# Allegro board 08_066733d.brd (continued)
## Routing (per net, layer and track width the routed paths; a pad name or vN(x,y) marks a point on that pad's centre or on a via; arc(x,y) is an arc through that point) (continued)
DMC0_DQ10: length 33.4
  TOP w0.203: U1.B12 v1(34.62,60.54) ; U8.C8 v1(29.02,79.14)
  BOTTOM w0.14: v1(34.62,60.54) 35.02,60.14 37.02,60.14 37.42,60.54 37.42,62.54 37.22,62.74 35.22,62.74 34.82,63.14 34.82,63.43 34.82,63.43 34.82,64.25 34.82,64.25 34.82,64.43 34.82,64.43 34.82,64.74 34.02,65.54 32.82,65.54 32.42,65.94 32.42,68.34 31.82,68.94 31.82,69.94 32.62,70.74 32.62,76.34 31.82,77.14 31.82,80.54 31.42,80.94 29.82,80.94 29.42,80.54 29.42,79.54 v1(29.02,79.14)
DMC0_DQ11: length 33.4
  TOP w0.203: U1.B10 v1(33.02,60.54) ; v1(28.22,73.54) 28.59,73.91 28.59,73.91 U8.C2
  BOTTOM w0.14: v1(28.22,73.54) 27.82,73.14 27.82,68.34 28.22,67.94 29.21,67.94 29.34,67.81 29.34,66.17 29.21,66.04 28.96,66.04 28.83,66.17 28.83,67.18 28.7,67.31 26.67,67.31 26.54,67.18 26.54,66.93 26.67,66.8 28.32,66.8 28.45,66.67 28.45,66.55 28.32,66.42 27.69,66.42 27.56,66.29 27.56,66.1 27.69,65.98 28.32,65.98 28.45,65.85 28.45,65.09 28.32,64.96 27.69,64.96 27.56,64.83 27.56,64.64 27.69,64.52 28.32,64.52 28.45,64.39 28.45,64.2 28.32,64.07 27.69,64.07 27.56,63.94 27.56,63.75 27.69,63.63 28.83,63.63 28.96,63.75 28.96,64.9 29.08,65.02 29.34,65.02 29.46,64.9 29.46,63.75 29.59,63.63 32.26,63.63 32.51,63.37 32.51,62.61 33.02,62.1 v1(33.02,60.54)
DMC0_DQ12: length 33.5
  TOP w0.203: v1(31.42,59.74) U1.C9 ; v1(26.62,78.34) 26.99,77.97 U8.A7
  BOTTOM w0.14: v1(31.42,59.74) 30.42,59.74 30.02,60.14 25.36,60.14 24.22,61.28 24.22,79.96 24.4,80.14 24.64,80.14 24.76,80.01 24.76,79.12 24.89,78.99 25.15,78.99 25.27,79.12 25.27,80.01 25.4,80.14 25.91,80.14 26.22,79.83 26.22,78.74 v1(26.62,78.34)
DMC0_DQ13: length 33.5
  TOP w0.203: U8.A2 27.05,73.97 v1(27.42,74.34) ; U1.A12 v1(33.82,61.34)
  BOTTOM w0.14: v1(33.82,61.34) 34.8,61.34 35.1,61.34 35.23,61.47 35.23,61.81 35.1,61.94 34.22,61.94 33.82,62.34 33.82,64.13 33.44,64.52 31.62,64.52 31.11,65.02 31.11,68.56 31.02,68.65 31.02,70.14 30.62,70.54 28.82,70.54 28.62,70.74 28.62,70.94 28.82,71.14 30.82,71.14 31.22,70.74 31.42,70.74 31.82,71.14 31.82,71.54 31.62,71.74 30.82,71.74 30.62,71.94 30.62,72.14 31.02,72.54 31.02,75.54 30.82,75.74 30.82,76.74 30.62,76.94 30.42,76.94 30.22,76.74 30.22,74.94 30.02,74.74 27.82,74.74 v1(27.42,74.34)
DMC0_DQ14: length 33.5
  TOP w0.203: v1(31.42,58.94) U1.D8 ; v1(27.42,79.14) 27.79,78.77 U8.B8
  BOTTOM w0.14: v1(27.42,79.14) 27.02,79.54 27.02,80.34 26.82,80.54 24.22,80.54 23.82,80.14 23.82,61.12 25.6,59.34 31.02,59.34 v1(31.42,58.94)
DMC0_DQ15: length 33.5
  TOP w0.203: v1(26.62,74.34) 26.99,74.71 26.99,74.71 U8.A3 ; v1(32.22,60.54) U1.B9
  BOTTOM w0.14: v1(26.62,74.34) 26.39,74.52 26.36,74.55 26.15,74.55 26.02,74.42 26.02,73.99 26.22,73.79 26.77,73.79 26.97,73.59 26.97,73.48 26.77,73.28 26.22,73.28 26.02,73.08 26.02,72.14 26.22,71.94 27.02,71.94 27.22,71.74 27.22,71.54 27.02,71.34 26.22,71.34 26.02,71.14 26.02,70.94 26.22,70.74 27.02,70.74 27.22,70.54 27.22,70.34 27.02,70.14 26.22,70.14 26.02,69.94 26.02,69.74 26.22,69.54 27.02,69.54 27.22,69.34 27.22,69.14 27.02,68.94 26.22,68.94 26.02,68.74 26.02,68.54 26.22,68.34 27.02,68.34 27.22,68.14 27.22,67.94 27.02,67.74 26.22,67.74 26.02,67.54 26.02,66.8 27.18,65.64 27.18,63.25 27.69,62.74 31.82,62.74 32.62,61.94 32.62,61.14 32.42,60.94 31.02,60.94 30.82,60.74 30.82,60.34 31.02,60.14 U1.B9 v1(32.22,60.54)
DMC0_LDM: length 33.4
  TOP w0.203: U8.E7 v1(29.82,78.34) ; v1(30.62,57.34) U1.E8
  L4_SIG w0.127: v1(30.62,57.34) 30.22,57.74 26.22,57.74 25.29,58.67 23.88,58.67 23.49,59.05 23.49,76.33 25.11,77.94 29.42,77.94 v1(29.82,78.34)
DMC0_LDQS: length 33.3
  TOP w0.203: v1(30.62,75.14) 30.99,74.77 U8.F3 ; U1.A6 v1(29.02,61.34)
  L4_SIG w0.076: v1(30.62,75.14) 30.72,74.94 30.7,74.83 30.35,74.49 30.35,73.47 29.72,72.83 29.72,72.14 29.97,71.88 29.97,71.63 29.59,71.25 29.59,70.74 29.97,70.36 29.97,67.18 29.84,67.06 26.92,67.06 26.67,66.8 26.67,66.29 26.92,66.04 29.84,66.04 29.97,65.91 29.97,65.28 29.84,65.15 26.92,65.15 26.67,64.9 26.67,64.45 26.92,64.2 30.1,64.2 30.23,64.07 30.23,63.88 30.1,63.76 27.43,63.76 27.18,63.5 27.18,62.75 27.43,62.5 29.21,62.5 29.46,62.24 29.46,61.86 v1(29.02,61.34)
DMC0_LDQS*: length 33.3
  TOP w0.203: U8.G3 31.79,74.77 v1(31.42,75.14) ; U1.A7 v1(29.82,61.34)
  L4_SIG w0.076: v1(29.82,61.34) 29.72,61.73 29.72,62.37 29.34,62.75 27.56,62.75 27.43,62.88 27.43,63.39 27.54,63.5 30.21,63.5 30.48,63.78 30.48,64.18 30.2,64.45 27.05,64.45 26.92,64.58 26.92,64.77 27.05,64.9 29.97,64.9 30.23,65.15 30.23,66.04 29.97,66.29 27.05,66.29 26.92,66.42 26.92,66.67 27.05,66.8 29.97,66.8 30.23,67.06 30.23,70.48 29.84,70.87 29.84,71.12 30.23,71.5 30.23,72.01 29.97,72.26 29.97,72.71 30.61,73.34 30.61,74.33 v1(31.42,75.14)
DMC0_ODT: length 41.2
  TOP w0.203: U8.K1 v1(33.82,72.74) ; v1(38.62,59.74) U1.B18
  L8_SIG w0.127: v1(33.82,72.74) 33.82,72.14 33.42,71.74 31.02,71.74 30.82,71.54 30.82,71.34 31.02,71.14 32.02,71.14 32.22,70.94 32.22,70.74 32.02,70.54 30.82,70.54 30.62,70.34 30.62,70.14 30.82,69.94 31.62,69.94 31.82,69.74 31.82,69.14 31.62,68.94 30.82,68.94 30.62,68.74 30.62,68.54 30.82,68.34 31.82,68.34 32.02,68.14 32.02,67.94 31.82,67.74 30.82,67.74 30.62,67.54 30.62,66.42 31.11,65.93 31.11,62.38 31.82,61.67 31.82,58.74 32.02,58.54 37.22,58.54 37.42,58.74 37.42,59.14 37.62,59.34 38.22,59.34 v1(38.62,59.74)
  BOTTOM w0.14: RN6.2 33.57,69.44 33.42,69.59 33.42,69.94 33.62,70.14 33.82,70.14 34.02,69.94 34.42,69.94 34.62,70.14 34.62,70.34 34.42,70.54 33.62,70.54 33.42,70.74 33.42,70.94 33.62,71.14 33.82,71.14 34.02,70.94 34.42,70.94 34.62,71.14 34.62,71.34 34.42,71.54 33.82,71.54 33.42,71.94 33.42,72.34 v1(33.82,72.74)
DMC0_RAS*: length 41.2
  TOP w0.203: v1(37.82,58.14) U1.D16 ; v1(33.02,74.34) 33.39,74.71 33.39,74.71 U8.J3
  L8_SIG w0.127: v1(37.82,58.14) 37.42,57.74 35.22,57.74 34.82,57.34 34.42,57.34 34.02,57.74 32.02,57.74 31.62,57.34 31.22,57.34 31.02,57.54 31.02,61.74 30.22,62.54 30.22,71.94 30.42,72.14 32.82,72.14 33.02,72.34 33.02,72.94 32.82,73.14 30.82,73.14 30.62,73.34 30.62,73.74 30.82,73.94 32.62,73.94 v1(33.02,74.34)
  BOTTOM w0.14: v1(33.02,74.34) 33.02,75.34 33.22,75.54 33.42,75.54 33.62,75.34 33.62,74.94 U8.J3 33.42,73.34 33.02,72.94 33.02,68.84 RN6.1
DMC0_RESET*: length 29.5
  TOP w0.14: U8.T2 39.6,73.35 39.6,72.32 39.22,71.94 R8.2
  TOP w0.203: v1(33.02,58.14) U1.D10 ; U8.T2 v1(38.62,73.54)
  L5_SIG w0.127: v1(33.02,58.14) 33.42,58.54 33.42,62.1 34.04,62.72 34.04,67.06 38.22,71.24 38.22,73.14 v1(38.62,73.54)
  BOTTOM w0.14: RN2.1 42.22,72.85 42.22,72.64 42.46,72.4 42.48,72.36 42.48,72.34 42.48,72.33 42.48,71.9 42.42,71.84 42.42,71.74 42.02,71.34 39.42,71.34 39.02,71.74 39.02,73.14 v1(38.62,73.54)
DMC0_RZQ: length 11.1
  TOP w0.203: v1(37.82,60.54) U1.B16
  BOTTOM w0.14: R1.1 42.82,54.94 42.29,55.47 42.29,59.47 41.62,60.14 38.22,60.14 v1(37.82,60.54)
DMC0_UDM: length 33.5
  TOP w0.203: U1.D12 v1(33.82,58.94) ; v1(29.02,75.14) 29.39,74.77 U8.D3
  BOTTOM w0.14: v1(29.02,75.14) 29.82,75.94 29.82,77.64 30.22,78.04 30.22,79.34 30.42,79.54 30.82,79.54 31.02,79.34 31.02,77.14 31.82,76.34 31.82,72.34 32.22,71.94 32.22,70.94 31.42,70.14 31.42,68.74 31.62,68.54 31.62,65.91 31.5,65.79 31.5,65.28 31.75,65.02 33.91,65.02 34.42,64.52 34.42,62.84 34.92,62.34 35.94,62.34 36.07,62.21 36.07,61.98 35.69,61.59 35.69,61.15 35.48,60.94 34.42,60.94 34.22,60.74 34.22,59.34 v1(33.82,58.94)
DMC0_UDQS: length 33.5
  TOP w0.203: U1.A9 v1(31.42,61.34) ; U8.C7 28.59,77.97 v1(28.22,78.34)
  BOTTOM w0.089: v1(28.22,78.34) 27.71,78.16 27.29,77.74 27.29,77.04 27.57,76.76 28.83,76.76 28.97,76.62 28.97,76.42 28.8,76.25 27.43,76.25 27.15,75.97 27.15,75.36 27.01,75.22 26.59,75.22 26.45,75.36 26.45,77.18 26.17,77.46 25.48,77.46 25.2,77.18 25.2,66.47 25.76,65.91 25.76,65.35 25.2,64.8 25.2,63.82 25.76,63.26 25.76,62.7 26.17,62.28 27.1,62.28 27.43,61.95 31.34,61.95 31.48,61.81 31.48,61.67 v1(31.42,61.34)
DMC0_UDQS*: length 33.4
  TOP w0.203: v1(28.22,77.54) 27.85,77.91 27.85,77.91 U8.B7 ; U1.A10 v1(32.22,61.34)
  BOTTOM w0.089: v1(32.22,61.34) 31.9,61.53 31.76,61.67 31.76,61.92 31.45,62.23 27.58,62.23 27.25,62.56 26.31,62.56 26.04,62.84 26.04,63.4 25.48,63.96 25.48,64.66 26.04,65.21 26.04,66.05 25.48,66.61 25.48,77.04 25.62,77.18 26.04,77.18 26.17,77.04 26.17,75.22 26.45,74.94 27.15,74.94 27.43,75.22 27.43,75.83 27.57,75.97 28.97,75.97 29.25,76.25 29.25,76.76 28.97,77.04 27.71,77.04 27.57,77.18 27.57,77.6 27.85,77.88 27.99,77.88 28.13,77.8 v1(28.22,77.54)
DMC0_VREF: length 12.4
  L8_SIG w0.305: v2(44.83,65.53) 44.58,65.53 44.58,56.54 v1(45.42,56.54)
  BOTTOM w0.406: 47.02,56.54 v1(45.42,56.54) 44.7,56.54
DMC0_WE*: length 41.1
  TOP w0.203: v1(33.02,58.94) U1.D11 ; U8.L3 v1(34.62,75.14)
  L4_SIG w0.127: v1(34.62,75.14) 35.02,75.14 35.22,75.34 35.22,75.54 35.02,75.74 34.42,75.74 34.22,75.94 34.22,76.14 34.42,76.34 35.82,76.34 36.02,76.54 36.02,76.74 35.82,76.94 33.22,76.94 33.02,76.74 33.02,76.54 33.22,76.34 33.62,76.34 33.82,76.14 33.82,75.14 34.22,74.74 34.22,73.14 34.42,72.94 34.42,72.54 34.22,72.34 33.62,72.34 33.42,72.14 33.42,71.94 33.62,71.74 34.42,71.74 34.62,71.54 34.62,71.34 34.42,71.14 33.62,71.14 33.42,70.94 33.42,70.74 33.62,70.54 34.42,70.54 34.62,70.34 34.62,70.14 34.42,69.94 33.62,69.94 33.42,69.74 33.42,63.75 32.88,63.21 32.88,62.8 32.62,62.54 32.62,59.34 v1(33.02,58.94)
  BOTTOM w0.14: RN1.3 41.22,77.19 40.98,76.95 39.42,76.95 38.82,76.35 35.23,76.35 34.62,75.74 v1(34.62,75.14)
EMMC_CLK: length 18
  TOP w0.14: v1(38.42,34.8) 38.09,35.13 U23.8
  L8_SIG w0.14: v1(49.1,37.8) 48.7,37.41 48.7,35.69 47.6,34.58 47.6,34.05 47.34,33.78 43.56,33.78 42.54,34.8 42.54,35.06 42.23,35.37 41.53,35.37 40.83,34.67 38.54,34.67 v1(38.42,34.8)
  BOTTOM w0.14: v1(38.42,34.8) 37.66,34.8 37.52,34.94 R138.2 ; R110.1 49.5,37.8 v1(49.1,37.8)
EMMC_CMD: length 38.7
  TOP w0.14: v1(49.28,35.05) 49.54,35.05 U19.M5 ; v1(22.16,37.97) 22.81,37.33 U12.3
  L8_SIG w0.127: v1(22.16,37.97) 21.78,37.97 21.65,38.1 21.65,38.71 21.88,38.94 23.26,40.32 24.32,40.32 25.4,41.4 27.62,41.4 29.02,40.01 30.65,40.01 31.1,39.56 33.59,39.56 34.34,38.81 34.36,38.81 34.38,38.8 34.48,38.8 34.99,38.29 39.12,38.29 39.61,37.8 44.21,37.8 44.89,38.48 49.28,38.48 49.91,37.85 49.91,35.69 v1(49.28,35.05)
  BOTTOM w0.14: R118.2 22.79,37.59 22.54,37.59 v1(22.16,37.97)
EMMC_DAT0: length 21.4
  TOP w0.14: U12.8 26.28,35.13 v1(26.61,34.8) ; v1(42.1,33.91) 42.13,33.88 U19.A3
  L8_SIG w0.127: v1(42.1,33.91) 41.21,33.02 36.26,33.02 35.24,32 32.51,32 31.73,32.78 30.16,32.78 28.96,33.99 27.42,33.99 v1(26.61,34.8)
  BOTTOM w0.14: R120.2 26.61,34.98 v1(26.61,34.8)
EMMC_DAT1: length 21.5
  TOP w0.14: U19.A4 v1(43.69,34.38) ; v1(27.56,36.83) U12.11
  L8_SIG w0.127: v1(43.69,34.38) 43.69,34.39 42.88,35.2 42.33,35.75 39.92,35.75 39.74,35.57 35.64,35.57 34.61,34.54 34.61,34.54 34.35,34.29 34.29,34.23 33.78,34.23 33.53,34.47 33.53,36.06 32.83,36.77 29.15,36.77 28.83,37.08 27.82,37.08 v1(27.56,36.83)
  BOTTOM w0.14: R121.2 v1(27.56,36.83)
EMMC_DAT2: length 31.5
  TOP w0.14: U21.3 22.81,32.07 v1(22.16,32.71) ; U19.A5 v1(42.1,34.88)
  L8_SIG w0.127: v1(42.1,34.88) 41.32,34.1 38.5,34.1 37.92,34.68 35.25,34.68 34.35,33.78 33.72,33.78 33.2,34.3 33.2,35.63 33.07,35.76 30.11,35.76 29.55,36.32 28.57,36.32 28.44,36.2 28.06,36.2 27.87,36.4 26.87,36.4 25.53,35.05 23.69,35.05 22.52,33.89 21.34,33.89 21.21,33.76 21.21,32.84 21.34,32.71 v1(22.16,32.71)
  BOTTOM w0.14: R122.2 22.79,32.33 22.54,32.33 v1(22.16,32.71)
EMMC_DAT3: length 28.2
  TOP w0.14: v1(22.16,29.92) 22.81,30.57 U21.6
  L2_PWR w0.14: v3(44.71,33.38) 44.09,32.77 v1(42.99,32.77)
  L8_SIG w0.127: v1(22.16,29.92) 22.6,30.36 27.76,30.36 28.34,30.94 29.29,30.94 29.71,31.37 31.74,31.37 32.95,30.15 33.54,30.15 34.2,29.49 35.52,29.49 37.03,30.99 37.03,31.15 37.61,31.74 41.96,31.74 v1(42.99,32.77)
  BOTTOM w0.14: v1(22.16,29.92) 22.59,30.35 22.83,30.35 R131.2
EMMC_DAT4: length 26.2
  TOP w0.14: v1(26.61,29.54) 26.28,29.87 U21.8
  L2_PWR w0.14: v3(44.71,33.88) 45.24,33.88 45.58,33.54 45.58,31.57 45.44,31.43 43.31,31.43 v1(42.93,31.81)
  L8_SIG w0.127: v1(26.61,29.54) 27.25,28.89 28.19,28.89 29.02,29.72 31.69,29.72 32.5,28.91 33.03,28.91 33.29,29.16 35.7,29.16 36.59,30.05 37.39,30.05 37.9,30.56 41.67,30.56 v1(42.93,31.81)
  BOTTOM w0.14: v1(26.61,29.54) 26.17,29.54 R132.2
EMMC_DAT5: length 21.2
  TOP w0.14: v1(27.75,31.76) 27.56,31.57 U21.11
  L2_PWR w0.14: v3(44.71,34.38) 44.6,34.38 43.56,33.34 v1(43.43,33.34)
  L8_SIG w0.127: v1(27.75,31.76) 27.8,31.81 30.04,31.81 30.15,31.7 31.88,31.7 32.44,31.13 33.92,31.13 34.29,31.5 36.15,31.5 37.34,32.69 37.92,32.69 38.54,32.07 41.28,32.07 42.55,33.34 v1(43.43,33.34)
  BOTTOM w0.14: v1(27.75,31.76) 27.69,31.83 27.18,31.83 R133.2
EMMC_DAT6: length 16.8
  TOP w0.14: U23.3 34.75,37.33 34.67,37.4 34.66,37.4 34.41,37.65 34.41,37.68 34.16,37.93 v1(34.16,38.04)
  L2_PWR w0.14: v3(44.71,34.88) 42.91,34.88 42.74,35.05 42.74,36.32 v1(43.24,36.83)
  L8_SIG w0.127: v1(34.16,38.04) 35.17,37.03 36.37,37.03 36.62,37.27 37.04,37.27 37.29,37.03 37.64,37.03 37.75,37.13 39.74,37.13 40.05,36.83 v1(43.24,36.83)
  BOTTOM w0.14: R134.2 34.73,37.33 34.55,37.51 34.55,37.53 34.16,37.91 v1(34.16,38.04)
EMMC_DAT7: length 15.9
  TOP w0.14: v1(34.17,34.72) 34.66,34.72 35.13,35.19 U23.6
  L2_PWR w0.14: v1(43.24,36.13) 43.96,36.13 v3(44.71,35.38)
  L8_SIG w0.127: v1(34.17,34.72) 34.99,35.53 34.99,36.45 35.18,36.64 36.4,36.64 36.65,36.39 37.01,36.39 37.26,36.64 39.69,36.64 40.2,36.13 v1(43.24,36.13)
  BOTTOM w0.14: v1(34.17,34.72) 34.17,34.25 34.31,34.11 R135.2
EMMC_EN*: length 109.6
  TOP w0.14: U12.13 26.97,37.83 27.61,38.47 v1(27.88,38.47) ; v1(23.95,33.86) 24.27,33.54 U21.1 ; U12.10 27.24,36.33 v1(27.62,35.94) ; v1(23.89,39.31) 24.27,38.93 U12.1 ; U21.10 27.3,31.07 v1(27.56,30.81) ; U23.10 39.24,36.33 v1(39.56,36.01) ; U12.4 22.36,36.83 v1(22.1,37.08) ; v1(28.07,33.21) 28.07,33.22 28.07,33.22 28.07,33.21 27.63,33.21 26.98,32.57 U21.13 ; v1(33.86,37.4) 33.98,37.4 34.55,36.83 U23.4 ; v2(16.11,59.12) U24.24 ; v1(35.7,39.31) 36.08,38.93 U23.1 ; U23.13 38.97,37.83 v1(39.58,38.44) ; U21.4 22.36,31.57 v1(22.1,31.83)
  L4_SIG w0.127: v2(16.11,59.12) 15.47,58.48 14.16,58.48 13.43,57.75 13.43,44.29 12.05,42.91 12.05,42.5 11.35,41.8 11.35,40.25 11.37,40.24 11.37,40.2 11.52,40.04 11.52,38.9 12.71,37.71 12.71,36.36 v1(13.07,36)
  L7_SIG w0.127: v1(33.86,37.4) 32.11,37.4 31.41,36.7 29.91,36.7 29.15,35.94 v1(27.62,35.94)
  L8_SIG w0.127: v1(13.07,36) 14.73,36 16.29,34.44 18.25,34.44 20.89,37.08 v1(22.1,37.08)
  BOTTOM w0.14: v1(23.89,39.31) 25.97,39.31 26.35,39.69 26.66,39.69 v1(27.88,38.47) 28.33,38.47 28.96,37.85 28.96,36.45 28.45,35.94 v1(27.62,35.94) 26.68,35.94 25.92,36.7 22.48,36.7 v1(22.1,37.08) 21.84,37.08 20.83,36.07 20.83,34.35 R115.1 R114.2 21.07,32.84 21.84,32.07 21.85,32.07 v1(22.1,31.83) 22.43,31.5 22.55,31.5 22.57,31.48 23.53,31.48 23.55,31.5 25.92,31.5 26.61,30.81 v1(27.56,30.81) 28.32,30.81 28.96,31.44 28.96,32.37 28.11,33.21 v1(28.07,33.21) 28.07,33.22 28.07,33.22 28.07,33.21 27.21,34.07 25.94,34.07 25.55,33.68 24.13,33.68 v1(23.95,33.86) ; 39.56,38.44 v1(39.56,36.01) 38.73,36.01 38.04,36.7 37.33,36.7 37.01,36.39 36.65,36.39 36.33,36.7 34.49,36.7 33.86,37.33 v1(33.86,37.4) ; 39.56,38.44 39.56,39.05 38.99,39.62 37.78,39.62 37.47,39.31 v1(35.7,39.31) ; 39.56,38.44 v1(39.58,38.44)
EMMC_SOM_EN*: length 103.5
  TOP w0.14: v1(28.27,36.63) 28.64,36.63 28.83,36.83 U20.4 ; v1(33.46,29.6) 33.46,29.6 33.46,29.59 33.4,29.65 33.4,30.73 33.07,31.07 U22.10 ; v1(29.84,39.24) 30.17,38.91 U20.1 ; v1(32.77,35.05) 33.34,35.63 33.34,36 33.09,36.25 33.08,36.25 33.01,36.33 U20.10 ; U25.4 34.24,31.57 33.92,31.25 33.92,31.11 33.92,31.11 33.92,30.47 v1(33.91,30.47) ; U25.13 v1(39.49,32.57) ; v1(35.94,33.97) 36.08,33.83 U25.1 ; U24.1 v2(16.86,60.58) ; U22.4 28.83,31.57 28.64,31.37 v1(28.27,31.37) ; U22.1 30.17,33.77 v1(30.04,33.91) ; U20.13 v1(32.62,38.4) ; U25.10 v1(39.45,31.07) ; U22.13 v1(32.62,33.21)
  L4_SIG w0.127: v2(16.86,60.58) 16.86,58.86 14.82,56.82 14.82,54.6 15.28,54.14 15.28,49.76 14.54,49.02 14.54,48.26 14.93,47.87 14.93,44.16 13.84,43.08 13.84,42.8 13.04,41.99 12.01,41.99 11.68,41.67 11.68,40.39 11.87,40.2 11.87,39.05 13.04,37.88 13.04,36.73 13.77,36 13.77,34.16 13.34,33.72 v1(11.56,33.72)
  L5_SIG w0.127: v1(33.46,29.6) 33.46,29.6 32.62,30.44 v1(32.62,33.21) ; v1(39.45,31.07) 39.45,32.53 v1(39.49,32.57) 39.04,33.02 36.89,33.02 v1(35.94,33.97)
  L7_SIG w0.127: v1(28.27,36.63) 29.01,36.63 29.84,37.47 v1(29.84,39.24) 30.16,39.24 31,38.4 v1(32.62,38.4) ; v1(28.27,31.37) 29.66,32.77 32.18,32.77 v1(32.62,33.21) 32.96,33.21 33.15,33.4 33.15,34.67 v1(32.77,35.05)
  L8_SIG w0.127: v1(28.27,31.37) 28.2,31.31 26.8,31.31 26.74,31.37 21.95,31.37 21.8,31.51 19.29,31.51 17.78,33.02 15.94,33.02 15.24,33.72 v1(11.56,33.72) ; v1(35.94,33.97) 35.24,33.97 34.66,33.39 34.66,33.16 34.35,32.85 33.94,32.85 33.58,33.21 v1(32.62,33.21) 30.73,33.21 v1(30.04,33.91)
  BOTTOM w0.14: 33.46,29.6 v1(33.46,29.6) ; 33.46,29.6 33.46,30.04 33.88,30.45 33.88,30.48 33.92,30.48 33.92,30.47 v1(33.91,30.47) ; 33.46,29.6 33.46,29.59 33.59,29.59 33.98,29.2 R116.2 R117.1 ; v1(32.77,35.05) 32.19,35.62 32.19,37.97 v1(32.62,38.4)
HADC0_VIN0: length 45.4
  TOP w0.203: v1(41.02,54.14) U1.K20
  L5_SIG w0.127: v1(61.72,27.3) 62.23,27.81 62.23,29.21 61.85,29.59 61.15,29.59 60.01,30.73 57.85,30.73 57.49,30.38 54.99,30.38 53.66,31.71 53.66,34.73 51.66,36.73 51.66,42.63 50.16,44.13 50.16,51.18 47.21,54.14 v1(41.02,54.14)
  BOTTOM w0.14: v1(61.72,27.3) 61.59,27.43 J1.47
HADC0_VIN1: length 41.4
  TOP w0.203: v1(41.02,52.54) U1.L20
  L5_SIG w0.127: v1(61.72,28.19) 61.15,27.62 57.85,27.62 56.08,29.39 54.2,29.39 50.65,32.94 50.65,42.13 47.62,45.15 47.62,49.72 46.61,50.74 44.32,50.74 42.52,52.54 v1(41.02,52.54)
  BOTTOM w0.14: v1(61.72,28.19) 61.6,28.07 J1.49
HADC0_VIN2: length 40.8
  TOP w0.203: v1(40.22,54.14) U1.K19
  L5_SIG w0.127: v1(40.22,54.14) 40.82,53.54 45.08,53.54 46.18,52.44 46.94,52.44 49.78,49.59 49.78,43.97 51.31,42.44 51.31,36.58 53.28,34.61 53.28,31.56 54.79,30.05 57.67,30.05 57.98,30.35 58.74,30.35 58.87,30.23 v1(58.87,29.77)
  BOTTOM w0.14: J1.51 59.05,28.7 58.8,28.96 58.8,29.77 v1(58.87,29.77)
HADC0_VIN3: length 42.7
  TOP w0.203: v1(39.42,52.54) U1.L19
  L5_SIG w0.127: v1(39.42,52.54) 39.92,53.04 42.72,53.04 44.52,51.24 46.82,51.24 48.01,50.05 48.01,45.24 50.98,42.27 50.98,36.44 52.95,34.47 52.95,31.32 54.55,29.72 56.71,29.72 57.15,29.27 59.69,29.27 60.01,28.96 v1(61.72,28.96)
  BOTTOM w0.14: J1.53 61.34,29.34 v1(61.72,28.96)
HADC0_VIN4: length 35.3
  TOP w0.203: v1(40.22,50.14) U1.P19
  L7_SIG w0.127: v1(40.22,50.14) 40.94,50.86 43.4,50.86 44.72,49.54 46.85,49.54 48.13,48.26 48.13,42.9 52.58,38.46 52.58,33.51 53.78,32.3 53.78,28.51 v1(54.67,27.62)
  BOTTOM w0.14: J1.48 54.86,27.43 v1(54.67,27.62)
HADC0_VIN5: length 34.9
  TOP w0.14: v1(41.02,50.14) U1.P20
  L7_SIG w0.127: v1(55.25,27.94) 55.25,27.43 54.86,27.05 54.48,27.05 53.34,28.19 53.34,32.15 52.2,33.3 52.2,38.27 47.74,42.73 47.74,48.12 46.72,49.14 42.02,49.14 v1(41.02,50.14)
  BOTTOM w0.14: v1(55.25,27.94) 55.37,28.07 J1.50
HADC0_VIN6: length 37.7
  TOP w0.14: v1(45.42,52.54) 44.82,53.14 42.62,53.14 41.25,51.77 40.44,51.77 40.43,51.75 40.21,51.75 U1.M19
  L7_SIG w0.127: v1(55.25,28.96) 54.61,29.59 54.61,32.41 53.28,33.74 53.28,38.73 50.48,41.53 50.48,50.78 48.72,52.54 v1(45.42,52.54)
  BOTTOM w0.14: J1.52 55.5,28.7 v1(55.25,28.96)
HADC0_VIN7: length 36.2
  TOP w0.203: v1(40.22,50.94) U1.N19
  L7_SIG w0.127: v1(40.22,50.94) 40.52,51.24 48.32,51.24 50.04,49.53 50.04,41.47 52.95,38.56 52.95,33.6 54.23,32.32 v1(54.23,28.96)
  BOTTOM w0.14: J1.54 56.58,29.44 54.74,29.44 v1(54.23,28.96)
ID0: length 21.7
  TOP w0.14: v2(52.2,10.54) 53.09,10.54 R136.2 53.22,9.6 52.83,9.2 U26.1
  L8_SIG w0.127: v1(39.88,4.44) 40.32,4.89 40.32,6.1 41.15,6.92 48.7,6.92 49.34,7.56 49.34,8.89 50.99,10.54 v2(52.2,10.54)
  BOTTOM w0.14: v1(39.88,4.44) 39.42,4.83 J2.76
ID1: length 17
  TOP w0.14: 52.45,5.84 52.45,7.19 U26.3 ; 52.45,5.84 50.42,5.84 49.28,6.98 41.28,6.98 v1(40.13,8.13) ; 52.45,5.84 R137.2
  BOTTOM w0.14: J2.78 40.05,8.05 v1(40.13,8.13)
INTVCC: length 16.7
  TOP w0.254: v2(24.83,13.08) 23.24,13.08 22.55,13.77 R100.2 20.43,14.62 20.42,14.62 20.23,14.81 20.23,14.81 20.05,14.99 VR1.3
  TOP w0.305: R94.2 v2(15.34,12.17)
  L8_SIG w0.305: v2(15.34,12.17) 16,12.83 21.14,12.83 21.4,13.08 v2(24.83,13.08)
JTG0_TCK/SWCLK: length 63.8
  TOP w0.14: v1(5.46,28.83) 4.98,28.35 3.91,28.35 2.65,29.6 2.65,46.89 1.94,47.6 1.94,55.25 3.04,56.34 5.51,56.34 6.03,55.82 6.03,54.67 5.08,53.72
  TOP w0.203: v1(27.42,60.54) U1.B4
  L8_SIG w0.127: 5.08,53.72 7.75,56.39 12.67,56.39 13.22,56.94 16.52,56.94 18.92,59.34 23.97,59.34 24.77,60.14 27.02,60.14 v1(27.42,60.54)
  BOTTOM w0.14: J3.50 5.59,28.7 v1(5.46,28.83)
JTG0_TD0/SW0: length 73.8
  TOP w0.14: P6.6 6.48,53.85 6.48,56.13 5.71,56.9 v2(2.16,56.9) 1.46,56.2 1.46,47.12 1.97,46.61 1.97,28.64 3.56,27.05 7.49,27.05 v1(8.26,27.81)
  TOP w0.203: v1(26.62,61.34) U1.A3
  L8_SIG w0.127: v2(2.16,56.9) 2.72,57.45 10.92,57.45 13.91,60.45 15.68,60.45 17.07,61.84 26.12,61.84 v1(26.62,61.34)
  BOTTOM w0.14: v1(8.26,27.81) 8,28.07 J3.52
JTG0_TDI: length 81.4
  TOP w0.14: 5.08,51.18 6.92,53.02 6.92,56.39 5.84,57.47 v2(1.46,57.47) 0.86,56.86 0.86,28.73 2.86,26.73 2.86,26.23 4.06,25.02 6.22,25.02 v1(8.26,27.05)
  TOP w0.203: v1(27.42,61.34) U1.A4
  L8_SIG w0.127: v1(27.42,61.34) 26.52,62.24 16.9,62.24 15.62,60.96 13.96,60.96 10.78,57.78 1.78,57.78 v2(1.46,57.47)
  BOTTOM w0.14: J3.54 7.87,27.43 v1(8.26,27.05)
JTG0_TMS/SWDIO: length 62.6
  TOP w0.14: P6.2 5.08,55.75 4.83,56.01 3.17,56.01 2.28,55.11 2.28,47.82 3.05,47.05 3.05,30.67 3.62,30.1 7.24,30.1 v1(8.26,29.08)
  TOP w0.203: v1(28.22,60.54) U1.B5
  L8_SIG w0.127: v1(28.22,60.54) 27.82,60.94 24.82,60.94 24.01,60.13 18.82,60.13 16.92,58.23 12.77,58.23 11.31,56.77 6.86,56.77 P6.2
  BOTTOM w0.14: J3.48 8,29.34 v1(8.26,29.08)
JTG0_TRST*: length 90.1
  TOP w0.14: v1(9.02,45.54) R79.1 R78.2 4.83,47.62 3.81,48.64 P6.9
  TOP w0.203: U1.C5 v1(29.02,59.74)
  L4_SIG w0.127: v1(3.81,47.18) 3.81,27.55 4.31,27.05 4.95,27.05 v1(5.46,26.54)
  L5_SIG w0.127: v1(9.02,45.54) 8.79,45.3 8.79,43.78 7.43,42.42 7.43,35.75 5.3,33.62 5.3,33.62 5.02,33.34 5.02,26.99 v1(5.46,26.54) ; v1(29.02,59.74) U1.C5 17.81,59.34 16.83,58.36 13.04,58.36 11.92,57.24 4.53,57.24 2.92,55.63 2.92,48.07 v1(3.81,47.18)
  BOTTOM w0.14: J3.56 5.72,26.8 v1(5.46,26.54)
LTC3310_EN: length 2.3
  TOP w0.254: U16.1 33.66,15.64 33.66,14.99 33.91,14.73 v2(33.91,14.54)
  BOTTOM w0.254: v2(33.91,14.54) 33.91,13.6 R92.2
MLB0_CLKN: length 38.3
  TOP w0.203: v1(30.62,45.34) U1.Y8
  L8_SIG w0.127: v1(61.72,41.4) 59.37,39.05 56.96,39.05 56.83,38.93 51.91,38.93 49.88,40.96 40.79,40.96 40.69,41.06 40.68,41.06 40.46,41.29 34.91,41.29 34.29,41.91 32.26,41.91 31.05,43.12 31.05,44.91 v1(30.62,45.34)
  BOTTOM w0.14: 61.21,41.4 v1(61.72,41.4) 61.21,41.4 ; 61.21,41.4 J1.91
MLB0_CLKP: length 33.5
  TOP w0.203: v1(31.42,45.34) U1.Y9
  L8_SIG w0.127: v1(58.42,40.26) 57.28,40.26 56.85,39.83 53.67,39.83 53.42,40.08 53.42,40.37 52.4,41.39 40.82,41.39 40.59,41.62 35.05,41.62 34.43,42.24 32.44,42.24 31.42,43.26 v1(31.42,45.34)
  BOTTOM w0.14: v1(58.42,40.26) 58.93,40.77 J1.89
MLB0_DATN: length 37.1
  TOP w0.203: v1(32.22,45.34) U1.Y10
  L8_SIG w0.127: v1(58.8,44.32) 59.82,43.31 59.82,41.4 59.18,40.77 53.66,40.77 52.71,41.72 41.97,41.72 41.92,41.77 41.9,41.77 40.93,42.74 39.4,42.74 38.72,42.05 37.73,42.05 37.13,42.65 36.71,42.65 36.63,42.57 33.08,42.57 32.7,42.95 32.7,44.86 v1(32.22,45.34)
  BOTTOM w0.14: J1.99 59.18,43.94 v1(58.8,44.32)
MLB0_DATP: length 32
  TOP w0.203: v1(33.82,45.34) U1.Y11
  L8_SIG w0.127: v1(58.8,43.56) 59.31,43.05 59.31,41.53 59.05,41.27 57.72,41.27 57.21,41.78 53.72,41.78 53.4,42.1 42.04,42.1 40.42,43.71 34.96,43.71 33.82,44.86 v1(33.82,45.34)
  BOTTOM w0.14: v1(58.8,43.56) 59.05,43.31 J1.97
MLB0_SIGN: length 28.5
  TOP w0.203: v1(34.62,45.34) U1.Y12
  L8_SIG w0.127: v1(58.8,42.8) 58.29,42.29 57.91,42.29 57.47,42.74 48.32,42.74 48.02,42.43 44.87,42.43 44.5,42.8 44.5,43.19 44.01,43.69 41.28,43.69 40.92,44.04 37.38,44.04 36.86,44.56 34.95,44.56 34.62,44.89 v1(34.62,45.34)
  BOTTOM w0.14: J1.95 58.93,42.67 v1(58.8,42.8)
MLB0_SIGP: length 27
  TOP w0.203: v1(35.42,45.34) U1.Y13
  L8_SIG w0.127: v1(58.04,42.8) 57.72,43.12 48.96,43.12 47.51,44.56 41.2,44.56 41.01,44.37 37.52,44.37 37,44.89 35.87,44.89 v1(35.42,45.34)
  BOTTOM w0.14: J1.93 59.28,42.04 59.02,42.29 58.55,42.29 v1(58.04,42.8)
PA_00/SPI2_MISO/OSPI_MISO/SMC0_D00: length 63.5
  TOP w0.203: U1.K2 v1(25.82,54.14)
  L4_SIG w0.127: v1(25.82,54.14) 25.22,53.54 22.42,53.54 21.22,52.34 21.22,47.57 18.54,44.89 18.54,42.35 19.34,41.55 19.34,40.58 19.61,40.31 v1(19.61,39.36) 19.61,35.93 18.81,35.13 18.81,28.65 21.22,26.24 21.22,18.15 22.11,17.26 22.11,10.17 v1(21.27,9.33)
  L8_SIG w0.127: v1(21.27,9.33) 21.27,8.83 21.4,8.7 21.4,7.75 20.89,7.24 18.29,7.24 16.76,5.71 v1(16.76,4.44)
  BOTTOM w0.14: v1(16.76,4.44) 16.56,4.24 J2.3 ; R52.2 v1(19.61,39.36)
PA_01/SPI2_MOSI/OSPI_MOSI/SMC0_D01: length 75.6
  TOP w0.14: U4.15 10.6,30.61 v2(10.99,30.23)
  TOP w0.203: U1.L3 v1(26.62,52.54)
  L4_SIG w0.127: v1(16.89,1.65) 15.62,2.92 10.1,2.92 7.72,5.3 7.72,19.47 9.72,21.46 9.72,28.96 v2(10.99,30.23)
  BOTTOM w0.14: v1(16.89,1.65) 17.19,1.95 J2.5 ; v1(26.62,52.54) 27.02,52.14 27.02,49.94 26.82,49.74 25.02,49.74 24.62,49.34 24.62,45.64 23.43,44.45 23.43,40.7 23.2,40.47 22.02,40.47 20.55,39 20.55,36.84 18.71,35 18.71,32.91 18.12,32.32 11.19,32.32 11.05,32.18 11.05,30.29 v2(10.99,30.23)
PA_02/SPI2_D2/OSPI_D2/TWI3_SCL/SMC0_D02/TM0_ACLK3: length 79.2
  TOP w0.14: U10.2 v2(10.09,41.27)
  TOP w0.203: v1(25.82,52.54) U1.L2
  L4_SIG w0.127: v1(17.65,4.44) 17.02,3.81 13.91,3.81 12.95,4.76 12.95,16.95 14.22,18.22 14.22,31.81 13.45,32.59 11.37,32.59 11.13,32.83 11.13,33.9 12.19,34.96 12.19,37.76 11.19,38.76 10.33,38.76 10.09,39 v2(10.09,41.27)
  BOTTOM w0.14: J2.7 17.83,4.27 v1(17.65,4.44) ; v2(10.09,41.27) 10.09,39.12 10.35,38.86 17.97,38.86 19.49,40.39 21.4,40.39 21.91,40.89 21.91,43.69 24.22,46 24.22,50.14 24.62,50.54 26.02,50.54 26.22,50.74 26.22,52.14 v1(25.82,52.54)
PA_03/SPI2_D3/OSPI_D3/TWI3_SDA/SMC0_D03: length 71
  TOP w0.14: U5.2 v2(12.26,41.27)
  TOP w0.203: v1(28.22,52.54) U1.L5
  L4_SIG w0.127: v1(18.29,1.65) 18.85,2.21 18.85,5.6 17.86,6.59 15.72,6.59 14.59,7.71 14.59,9.35 13.34,10.6 13.34,16.64 14.55,17.86 14.55,35.68 13.37,36.86 13.37,38.06 12.26,39.18 12.26,41.26 v2(12.26,41.27) 13.01,41.27 14.22,42.48 14.22,42.99 15.53,44.3 v1(15.53,48.03)
  L5_SIG w0.127: v1(28.22,52.54) 27.82,52.14 24.82,52.14 23.99,51.31 18.81,51.31 v1(15.53,48.03)
  BOTTOM w0.14: v1(18.29,1.65) 18.46,1.83 J2.9
PA_04/SPI2_CLK/OSPI_CLK/SMC0_D04: length 98.3
  TOP w0.14: R49.1 v2(10.99,27.62)
  TOP w0.203: v1(27.42,52.54) U1.L4
  L5_SIG w0.127: v1(24.66,39.79) 24.32,39.46 24.32,38.01 23.88,37.56 23.88,35.75 24.38,35.24 24.38,33.4 24.89,32.89 24.89,30.1 25.4,29.59 25.4,28.51 22.68,25.79 22.68,17.89 23.56,17.02 23.56,2.1 22.61,1.14 19.56,1.14 v1(19.05,1.65)
  L7_SIG w0.127: v1(24.66,39.79) 24.38,40.07 22.16,40.07 20.76,38.67 20.76,35.14 21.16,34.75 21.52,34.75 21.52,34.75 23.82,34.75 24.38,34.19 24.38,33.68 23.95,33.25 23.95,30.47 25.34,29.08 25.34,28.63 21.68,24.97 14.21,24.97 11.56,27.62 v2(10.99,27.62)
  BOTTOM w0.14: v1(27.42,52.54) 27.82,52.14 27.82,44.84 26.67,43.69 26.67,40.83 25.63,39.79 v1(24.66,39.79) ; v1(19.05,1.65) 19.1,1.7 J2.11
PA_05/SPI2_SEL1B/OSPI_SEL1B/SMC0_D05/SPI2_SSB: length 68.8
  TOP w0.14: U9.2 v2(16.32,41.27)
  TOP w0.203: v1(25.82,51.74) U1.M2
  L4_SIG w0.127: v2(16.32,41.27) 17.28,41.27 17.93,40.61 17.93,39.85 18.06,39.72 18.06,39.28 15.75,36.96 15.75,36.55 14.88,35.69 14.88,17.42 13.72,16.26 13.72,10.86 14.92,9.65 14.92,7.85 15.85,6.92 18.35,6.92 19.81,5.46 v1(19.81,1.65)
  BOTTOM w0.14: v1(25.82,51.74) 25.42,51.34 24.12,51.34 23.52,50.74 23.52,46.13 22.99,45.59 16.62,45.59 16.32,45.29 v2(16.32,41.27) ; J2.13 19.73,1.73 v1(19.81,1.65)
PA_06/SPI0_CLK/UART0_TXB/OSPI_D4/SMC0_D06/TM0_ACLK1: length 124.9
  TOP w0.14: v2(20.19,75.82) 18.32,75.82 U7.9
  TOP w0.203: U1.M3 v1(26.62,51.74)
  L4_SIG w0.127: v2(20.19,75.82) 14.35,69.98 14.35,67.44 13.84,66.93 13.84,65.79 18.48,61.15 18.48,60.01 15.15,56.68 15.15,54.74 15.61,54.28 15.61,49.32 15.02,48.73 v1(15.02,48.73)
  L5_SIG w0.127: v1(20.32,4.44) 20.83,4.95 20.83,5.59 23.18,7.94 23.18,16.7 22.35,17.53 22.35,26.42 v1(24.26,28.32)
  L7_SIG w0.127: v1(24.26,28.32) 23.61,28.32 23.48,28.45 23.48,29.35 22.65,30.18 22.65,33.59 22.4,33.84 22.38,33.84 22.34,33.89 20.88,33.89 19.77,34.99 19.77,38.17 22.19,40.58 22.19,41.12 22.8,41.73 31.83,41.73 32.98,42.89 32.98,50.2 31.84,51.34 27.02,51.34 v1(26.62,51.74)
  L8_SIG w0.127: v1(15.02,48.73) 15.02,49.44 15.76,50.17 17.99,50.17 19.15,51.34 26.22,51.34 v1(26.62,51.74)
  BOTTOM w0.14: J2.15 20.32,3.13 v1(20.32,4.44) 19.88,4.89 17.13,4.89 16.56,5.46 J2.4
PA_07/SPI0_MISO/UART0_RXB/OSPI_D5/SMC0_D07/TM0_ACI0: length 129
  TOP w0.14: v1(20.95,1.65) 19.75,2.86 16.76,2.86 15.94,3.68 15.94,4.44 17.02,5.52 17.02,7.62 v1(17.53,8.13) ; U7.12 v2(16.19,77.74)
  TOP w0.203: v1(25.82,50.94) U1.N2
  L4_SIG w0.127: v1(20.95,1.65) 22.1,2.79 26.29,2.79 27.05,3.56 27.05,5.71 23.43,9.33 23.43,17.47 22.21,18.69 22.21,26.65 19.8,29.06 19.8,33.77 20.89,34.86 20.89,39.75 21.78,40.64 21.78,44.5 22.42,45.14 22.42,49.14 24.22,50.94 v1(25.82,50.94) ; v2(16.19,77.74) 14.94,78.99 13.97,78.99 13.84,78.87 13.84,77.72 14.67,76.9 14.67,76.33 13.59,75.25 13.59,73.66 8.89,68.96 8.89,64.45 8.45,64.01 8.45,59.69 9.08,59.05 9.08,58.17 10.79,56.45 v2(10.79,49.91)
  L7_SIG w0.127: v2(10.79,49.91) 11.48,50.6 19.01,50.6 19.46,50.15 21.46,50.15 22.25,50.94 v1(25.82,50.94)
  BOTTOM w0.14: v1(17.53,8.13) 17.19,7.79 J2.6 ; J2.17 20.95,3.04 v1(20.95,1.65)
PA_08/SPI0_MOSI/UART0_RTSB/OSPI_D6/SMC0_D08/TM0_ACLK2: length 117.7
  TOP w0.14: U7.2 11.4,78.39 v2(11.05,78.74) ; v1(17.65,5.33) 18.16,5.84 19.05,5.84 20,4.89 20.89,4.89 v1(21.34,4.44)
  TOP w0.203: v1(25.82,50.14) U1.P2
  L4_SIG w0.127: v1(21.34,35.18) 21.78,35.62 22.41,35.62 22.67,35.88 22.67,36.51 22.53,36.65 21.92,36.65 21.67,36.9 21.67,38.75 23.18,40.26 23.18,44.64 23.82,45.28 23.82,48.14 v1(25.82,50.14) ; v2(11.05,78.74) 9.27,78.74 7.87,77.34 7.87,67.69 6.48,66.29 6.48,59.94 6.98,59.44 6.98,48.2 v2(10.79,44.39)
  L5_SIG w0.127: v1(17.65,5.33) 19.11,6.79 20.95,6.79 21.46,7.3 21.46,8.76 22.47,9.77 22.47,16.4 21.59,17.27 21.59,33.02 21.34,33.27 v1(21.34,35.18)
  L7_SIG w0.127: v2(10.79,44.39) 13.6,47.2 16.65,47.2 17.7,48.24 18.39,48.24 18.79,48.64 24.32,48.64 v1(25.82,50.14)
  BOTTOM w0.14: J2.8 17.83,5.51 v1(17.65,5.33) ; J2.19 21.64,4.14 v1(21.34,4.44)
PA_09/SPI0_SEL1B/UART0_CTSB/OSPI_D7/SMC0_D09/SPI0_SSB: length 123.2
  TOP w0.14: v1(22.48,1.65) 20.83,3.3 20.45,3.3 v1(18.41,5.33) ; U7.5 13.13,76.44 13.27,76.58 v2(13.84,76.58)
  TOP w0.203: v1(26.62,50.94) U1.N3
  L4_SIG w0.127: v1(26.62,50.94) 26.22,50.54 24.62,50.54 23.49,49.41 23.49,48.88 23.49,48.88 23.49,45.59 22.12,44.22 22.12,40.34 21.34,39.56 v1(21.34,35.88) ; v2(10.79,45.47) 9.4,46.86 9.4,55.88 7.43,57.85 7.43,63.75 8.38,64.71 8.38,69.34 12.95,73.91 12.95,75.69 v2(13.84,76.58)
  L5_SIG w0.127: v1(22.48,1.65) 21.15,2.98 19.81,2.98 19.62,3.18 19.62,6.03 19.94,6.35 21.08,6.35 22.8,8.06 22.8,16.57 21.97,17.4 21.97,29.02 23.51,30.56 23.51,35.25 23.14,35.62 21.59,35.62 v1(21.34,35.88)
  L7_SIG w0.127: v1(26.62,50.94) 26.23,50.55 24.38,50.55 23.62,49.78 19.18,49.78 18.8,50.16 15.49,50.16 v2(10.79,45.47)
  BOTTOM w0.14: v1(22.48,1.65) 22.27,1.86 J2.21 ; J2.10 18.46,5.38 v1(18.41,5.33)
PA_10/TWI0_SCL/SPI1_CLK/TM0_TMR0/SMC0_D10: length 68.3
  TOP w0.14: v1(20.95,8.13) 21.84,7.24 21.84,3.81 23.24,2.41 24.51,2.41 v1(25.27,1.65)
  TOP w0.203: v1(28.22,51.74) U1.M5
  L4_SIG w0.127: v1(28.22,51.74) 27.82,52.14 22.62,52.14 21.62,51.14 21.62,46.7 19.43,44.51 19.43,43.6 19.24,43.41 19.24,42.3 19.67,41.87 19.67,40.72 20.13,40.26 20.13,35.98 19.14,34.99 19.14,28.79 21.55,26.37 21.55,18.34 22.54,17.35 22.54,9.72 v1(20.95,8.13)
  BOTTOM w0.14: v1(20.95,8.13) 20.45,8.64 19.99,8.64 19.73,8.38 J2.14 ; J2.31 25.45,1.83 v1(25.27,1.65)
PA_11/TWI0_SDA/SPI1_MISO/HADC0_EOC_OUT/SMC0_D11/TM0_ACI4: length 74.4
  TOP w0.203: v1(29.82,46.94) U1.V7
  L4_SIG w0.127: v1(29.82,46.94) 30.22,46.54 30.22,44.74 31.06,43.9 31.06,42.05 31.45,41.66 31.45,40.62 32.51,39.57 32.51,38.9 32.19,38.58 32.19,38.22 32.52,37.89 32.52,36.37 33.53,35.37 33.53,33.25 34.02,32.75 34.02,32.4 33.77,32.14 33.48,32.14 31.11,29.78 31.11,28.96 32.38,27.69 34.08,27.69 34.98,26.79 34.98,21.09 37.91,18.16 37.91,8.76 35.05,5.91 35.05,5.22 35.5,4.78 35.5,3.75 34.35,2.6 v1(34.35,1.71)
  L8_SIG w0.127: v1(34.35,1.71) 33.66,2.41 27.05,2.41 v1(26.29,1.65) 25.59,2.35 22.42,2.35 20.83,3.94 20.83,4.83 v1(20.32,5.33)
  BOTTOM w0.14: J2.16 20.32,6.64 v1(20.32,5.33) ; J2.33 26.08,1.86 v1(26.29,1.65)
PA_12/FLG0/SPI1_MOSI/TM0_TMR1/SMC0_D12: length 67.3
  TOP w0.203: v1(30.62,47.74) U1.U8
  L4_SIG w0.127: v1(30.62,47.74) 31.02,47.34 31.02,45.04 31.43,44.63 31.43,42.14 31.78,41.79 31.78,40.76 32.84,39.7 32.84,38.81 33.34,38.31 33.34,36.03 33.86,35.5 33.86,35.44 34.11,35.19 34.47,35.19 34.67,34.99 34.67,31.88 33.66,30.86 33.02,30.86 32.13,29.97 32.13,29.21 32.58,28.77 34.04,28.77 35.31,27.5 35.31,21.23 38.25,18.29 38.25,8.03 v1(35.56,5.33)
  L8_SIG w0.127: v1(21.34,5.33) 21.84,5.84 29.08,5.84 30.02,4.9 35.13,4.9 v1(35.56,5.33)
  BOTTOM w0.14: J2.18 21,5.67 v1(21.34,5.33)
PA_13/FLG1/SPI1_SEL1B/TM0_TMR2/SMC0_D13/SPI1_SSB: length 52.8
  TOP w0.203: v1(28.22,45.34) U1.Y5
  L4_SIG w0.127: v1(31.37,8.13) 29.84,9.65 29.84,15.53 30.11,15.8 30.11,17.6 28.5,19.21 28.5,29.29 29.13,29.93 29.13,32.21 28.52,32.82 28.52,33.52 26.8,35.24 26.8,37.66 27.36,38.21 27.36,38.72 28.22,39.59 v1(28.22,45.34)
  L7_SIG w0.14: v1(31.37,8.13) 30.35,7.11 22.99,7.11 v1(21.97,8.13)
  BOTTOM w0.14: J2.20 21.64,7.79 v1(21.97,8.13)
PA_14/TWI2_SCL/SPI1_D2/UART1_RXB/SMC0_D14/TM0_ACI1: length 13.3
  TOP w0.203: v1(29.02,46.94) U1.V6
  L8_SIG w0.127: v1(37.66,42.74) 37.41,42.98 36.58,42.98 36.5,42.9 33.4,42.9 33.1,43.2 33.1,45.95 32.53,46.53 29.43,46.53 v1(29.02,46.94)
  BOTTOM w0.14: R13.1 v1(37.66,42.74)
PA_15/TWI2_SDA/SPI1_D3/UART1_TXB/SMC0_D15: length 12.5
  TOP w0.203: v1(31.42,48.54) U1.T9
  L8_SIG w0.127: v1(31.42,48.54) 31.81,48.15 32.36,48.15 32.61,47.9 32.61,47.02 33.43,46.2 33.43,44.55 34.59,43.38 38.09,43.38 v1(38.73,42.74)
  BOTTOM w0.14: R12.1 v1(38.73,42.74)
PB_00/MLB0_DAT/TWI1_SCL/UART1_RTSB/SMC0_AMS0B/TM0_ACI3: length 103.4
  TOP w0.203: v1(40.22,61.34) U1.A19
  L4_SIG w0.127: v1(58.04,43.56) 58.23,43.75 58.23,54.55 51.84,60.94 40.62,60.94 v1(40.22,61.34)
  L7_SIG w0.127: v1(58.04,43.56) 56.9,42.42 56.9,16.7 56.08,15.89 56.08,10.62 51.56,6.1 51.56,4.32 v1(50.67,3.43)
  L8_SIG w0.127: v1(26.54,4.44) 27.88,3.11 50.36,3.11 v1(50.67,3.43)
  BOTTOM w0.14: J1.100 57.66,43.94 v1(58.04,43.56) ; J2.35 26.72,4.27 v1(26.54,4.44)
PB_01/MLB0_SIG/TWI1_SDA/UART1_CTSB/SMC0_AREB/TM0_CLK: length 98.7
  TOP w0.203: v1(38.62,58.14) U1.E17
  L4_SIG w0.127: v1(38.62,58.14) 39.02,58.54 49.35,58.54 55.37,52.51 55.37,44.32 v1(54.86,43.81)
  L7_SIG w0.127: v1(50.67,4.44) 50.67,11.22 54.18,14.72 54.18,15.99 56.46,18.28 56.46,42.21 v1(54.86,43.81)
  L8_SIG w0.127: v1(27.56,4.44) 28.51,3.49 49.72,3.49 v1(50.67,4.44)
  BOTTOM w0.14: v1(54.86,43.81) 55.37,43.31 J1.98 ; J2.37 27.35,4.24 v1(27.56,4.44)
PB_02/MLB0_CLK/FLG3/LP1_ACK/SMC0_AWEB/TM0_ACLK4: length 74.4
  TOP w0.203: v1(37.82,57.34) U1.F16
  L4_SIG w0.127: v1(37.82,57.34) 38.22,56.94 41.52,56.94 41.92,57.34 48.51,57.34 53.85,52.01 v1(53.85,42.29)
  BOTTOM w0.14: J1.96 54.23,42.67 v1(53.85,42.29) 52.58,42.29 51.24,40.96 51.24,37.91 51.28,37.87 51.28,37.74 52.06,36.96 52.86,36.96 53,36.82 53,30.58 51.66,29.24 51.63,29.24 50.61,28.22 50.61,20.95 50.93,20.64 50.93,11.37 48.45,8.89 46.91,8.89 46.4,8.38 J2.98
PB_03/TM0_TMR3/FLG2/SPI2_SEL2B/SMC0_ADDR1/CNT0_UD: length 114.8
  TOP w0.203: v1(28.22,58.94) U1.D5
  L7_SIG w0.127: v1(28.22,58.94) 28.62,59.34 41.32,59.34 41.82,58.84 41.82,56.35 43.87,54.3 48.16,54.3 52.32,50.14 52.32,41.91 53.47,40.77 54.36,40.77 v1(54.86,40.26) 53.72,39.12 53.72,36.96 56.13,34.54 56.13,18.41 53.85,16.13 53.85,14.86 50.04,11.05 v1(50.04,2.16)
  L8_SIG w0.127: v1(23.11,4.44) 24.82,2.74 49.45,2.74 v1(50.04,2.16)
  BOTTOM w0.14: v1(54.86,40.26) 56.55,40.26 J1.88 ; J2.23 22.91,4.06 v1(23.11,4.44)
PB_04/TM0_TMR4/SPI1_RDY/LP0_ACK/SMC0_ADDR2/CNT0_ZM: length 167.6
  TOP w0.14: R111.1 v2(43.05,88.39) ; v1(46.48,4.44) 46.04,4.89 24.7,4.89 v1(24.26,5.33)
  TOP w0.203: v1(29.02,58.14) U1.E6
  L5_SIG w0.127: v1(53.85,41.27) 53.21,41.91 53.21,46.35 52.51,47.05 52.51,50.99 v1(49.53,53.97) ; v1(29.02,58.14) 29.42,58.54 29.42,61.54 28.82,62.14 22.92,62.14 21.21,63.85 21.21,82.87 24.64,86.3 37.08,86.3 39.18,88.39 v2(43.05,88.39)
  L8_SIG w0.127: v1(49.53,53.97) 47.37,53.97 45.84,55.5 42.68,55.5 42.04,56.14 29.52,56.14 29.02,56.64 v1(29.02,58.14)
  BOTTOM w0.14: J2.28 24.26,6.61 v1(24.26,5.33) ; J2.97 46.48,3.16 v1(46.48,4.44) 47.05,5.02 49.85,5.02 52.77,7.94 52.77,21.34 54.03,22.6 54.03,26.99 53.69,27.34 53.69,37.18 53.21,37.66 53.21,37.65 52.35,37.65 51.97,38.03 51.97,40.41 52.83,41.27 v1(53.85,41.27) 54.36,40.77 55.75,40.77 J1.90
PB_05/TM0_TMR5/SPI2_RDY/SPI0_SEL2B/SMC0_ADDR3/CNT0_DG: length 183.2
  TOP w0.14: R112.2 v2(50.16,88.46)
  TOP w0.203: v1(27.42,58.94) U1.C4
  L4_SIG w0.127: v2(50.16,88.46) 47.56,85.85 22.99,85.85 21.82,84.69 21.82,72.88 21.22,72.27 21.22,61.14 v1(19.82,59.74)
  L7_SIG w0.127: v1(27.42,58.94) 28.62,60.14 30.32,60.14 31.12,60.94 42.95,60.94 45.05,58.84 46.96,58.84 53.72,52.07 53.72,43.31 54.86,42.16 v1(54.86,41.27)
  L8_SIG w0.127: v1(52.2,11.43) 49.66,11.43 48.39,10.16 30.61,10.16 30.1,9.65 26.42,9.65 24.76,11.3 21.15,11.3 20.82,10.98 20.82,8.88 20.64,8.7 19.62,8.7 v1(19.05,8.13)
  BOTTOM w0.14: v1(52.2,11.43) 52.2,21.27 53.59,22.67 53.59,25.02 52.83,25.78 52.83,28.26 53.34,28.77 53.34,37.04 53.08,37.31 52.2,37.31 51.63,37.88 51.63,40.7 52.71,41.78 54.36,41.78 v1(54.86,41.27) 56.55,41.27 J1.92 ; v1(27.42,58.94) 27.02,58.54 23.9,58.54 23.49,58.94 20.62,58.94 v1(19.82,59.74) ; v1(19.05,8.13) 19.05,6.73 J2.12
PB_06/LP0_CLK/SPI1_SEL5B/TRACE0_CLK: length 63.6
  TOP w0.203: v1(27.42,46.94) U1.V4
  L5_SIG w0.127: v1(46.99,1.65) 45.41,3.23 33.1,3.23 31.94,4.38 31.94,5.44 29.84,7.53 29.84,8.57 28.57,9.84 28.57,29.37 29.51,30.31 29.51,34.15 29.78,34.42 29.78,34.96 29.46,35.28 29.46,37.35 28.45,38.37 28.45,39.05 28.26,39.24 28.26,40.62 28.26,44.27 27.82,44.71 27.82,46.54 v1(27.42,46.94)
  BOTTOM w0.14: J2.99 47.04,1.7 v1(46.99,1.65)
PB_07/LP0_D0/SPI2_SEL5B/TRACE0_D00: length 65.1
  TOP w0.203: v1(26.62,45.34) U1.Y3
  L5_SIG w0.127: v1(26.62,45.34) 26.62,44.88 26.81,44.69 26.81,40.76 25.72,39.66 25.72,38.23 26.24,37.71 26.24,35.61 25.98,35.36 25.98,33.6 26.49,33.09 26.49,30.09 26.11,29.71 26.11,28.78 26.48,28.41 26.48,18.22 25.73,17.47 25.73,15.42 26.29,14.86 26.29,8.13 28.07,6.35 28.07,3.94 29.44,2.57 38.2,2.57 39.62,1.14 45.21,1.14 v1(45.72,1.65)
  BOTTOM w0.14: J2.95 45.72,3.04 v1(45.72,1.65)
PB_08/LP0_D1/SPI1_SEL7B/TM0_TMR6/TRACE0_D01: length 66.7
  TOP w0.14: v1(44.96,1.65) 44.08,2.53 31.99,2.53 v1(31.11,1.65)
  TOP w0.203: v1(25.82,45.34) U1.Y2
  L5_SIG w0.127: v1(25.82,45.34) 25.82,44.86 26.48,44.2 26.48,40.89 25.15,39.56 25.15,35.14 25.6,34.68 25.6,33.51 26.16,32.96 26.16,30.23 25.78,29.84 25.78,28.64 26.04,28.38 26.04,18.41 24.19,16.57 24.19,8.64 27.05,5.78 27.05,3.68 28.64,2.1 30.67,2.1 v1(31.11,1.65)
  BOTTOM w0.14: v1(44.96,1.65) 45.13,1.83 J2.93
PB_09/LP0_D2/SPI2_SEL7B/TM0_TMR7/TRACE0_D02: length 63.2
  TOP w0.203: U1.Y4 v1(27.42,45.34)
  L4_SIG w0.127: v1(27.43,40.13) 26.81,40.75 26.81,44.15 27.42,44.76 v1(27.42,45.34)
  L5_SIG w0.127: v1(44.2,1.65) 42.95,2.9 30.38,2.9 29.21,4.06 29.21,7.37 27.56,9.02 27.56,14.57 26.25,15.88 26.25,17.43 27.11,18.29 27.11,29.84 26.92,30.04 26.92,32.72 27.36,33.16 27.36,34.68 26.57,35.47 26.57,37.84 26.17,38.24 26.17,39.65 26.65,40.13 v1(27.43,40.13)
  BOTTOM w0.14: v1(44.2,1.65) 44.5,1.95 J2.91
PB_10/LP0_D3/SPI1_SEL2B/TRACE0_D03: length 82.1
  TOP w0.14: v1(44.2,4.44) 43.31,3.56 30.61,3.56 v1(29.72,4.44) 28.96,3.68 23.11,3.68 v1(22.35,4.44)
  TOP w0.203: v1(28.22,47.74) U1.U5
  L4_SIG w0.127: v1(28.22,47.74) 27.82,47.34 27.82,43.56 27.86,43.52 27.86,39.83 27.6,39.56 26.29,39.56 26.16,39.43 26.16,38.12 26.43,37.86 26.43,35.76 26.05,35.38 26.05,33.54 26.56,33.03 26.56,30.6 26.1,30.14 26.1,29.4 27.84,27.66 27.84,18.94 28.51,18.27 28.51,15.37 28.91,14.97 28.91,7.5 29.59,6.82 32.74,6.82 33.4,6.16 33.4,5.08 31.88,3.56 30.61,3.56 v1(29.72,4.44)
  BOTTOM w0.14: v1(44.2,4.44) 43.86,4.06 J2.89 ; J2.22 22.35,6.61 v1(22.35,4.44)
PB_11/LP0_D4/SPI0_RDY/UART2_RXB/TM0_ACI2: length 55.1
  TOP w0.203: v1(29.02,47.74) U1.U6
  L5_SIG w0.127: v1(29.02,47.74) 29.41,47.35 30.89,47.35 31.03,47.2 31.03,47.11 31.03,47.1 31.03,43.71 31.43,43.31 31.43,38.35 31.11,38.04 31.11,35.28 31.13,35.27 31.13,30.35 35.48,25.99 35.48,18.74 36.45,17.78 36.45,16.18 37.11,15.52 37.11,10.63 36.64,10.16 36.64,6.98 38.18,5.45 38.18,5.15 38.44,4.89 42.74,4.89 v1(43.18,4.44)
  BOTTOM w0.14: J2.87 43.23,4.06 v1(43.18,4.44)
PB_12/LP0_D5/SPI2_SEL3B/UART2_TXB: length 56.8
  TOP w0.203: v1(28.22,46.94) U1.V5
  L5_SIG w0.127: v1(28.22,46.94) 28.62,46.54 29.22,46.54 29.42,46.34 29.42,43.73 31.1,42.05 31.1,38.53 30.78,38.21 30.78,35.15 30.8,35.13 30.8,29.72 29.29,28.21 29.29,20.75 31.09,18.95 31.09,10.57 35.1,6.56 35.1,4.59 35.75,3.94 41.91,3.94 v1(42.42,4.44)
  BOTTOM w0.14: J2.85 42.59,3.94 v1(42.42,4.44)
PB_13/LP0_D6/SPI1_SEL3B/UART2_RTSB: length 55.8
  TOP w0.14: v1(33.4,4.44) 33.95,3.9 40.98,3.9 v1(41.53,4.44)
  TOP w0.203: v1(28.22,46.14) U1.W5
  L5_SIG w0.127: v1(28.22,46.14) 28.62,45.74 28.62,43.55 28.59,43.52 28.59,40.76 28.59,39.8 29.84,38.54 29.84,35.47 30.47,34.85 30.47,33.3 29.84,32.68 29.84,29.23 28.96,28.34 28.96,18.86 29.95,17.87 29.95,10.38 30.78,9.54 30.78,7.89 33.4,5.27 v1(33.4,4.44)
  BOTTOM w0.14: v1(41.53,4.44) 41.96,3.94 J2.83
PB_14/LP0_D7/SPI0_SEL3B/UART2_CTSB: length 52.4
  TOP w0.203: v1(38.62,46.14) U1.W17
  L7_SIG w0.127: v1(38.62,46.14) 38.22,45.74 38.22,44.83 40.47,42.58 40.47,29.93 38.67,28.13 38.67,26.04 37.41,24.78 37.41,18.59 38.86,17.14 38.86,11.11 41.16,8.81 41.16,7.99 43.69,5.46 43.69,3.81 v1(41.53,1.65)
  BOTTOM w0.14: v1(41.53,1.65) 41.32,2.16 J2.81
PB_15/LP1_D0/SPI0_SEL4B/MIS0_CD/SMC0_ADDR4: length 45.2
  TOP w0.14: U20.6 v1(29.22,34.54)
  L4_SIG w0.127: v1(34.34,7.94) 31.08,11.2 31.08,19.04 28.83,21.29 28.83,28.03 29.69,28.89 29.69,30.17 29.46,30.39 29.46,33.39 29.22,33.63 v1(29.22,34.54)
  L8_SIG w0.127: v1(45.59,8.13) 44.97,7.51 34.77,7.51 v1(34.34,7.94)
  BOTTOM w0.14: J2.96 45.77,7.95 v1(45.59,8.13) ; J2.60 v1(34.34,7.94)
PB_15/LP1_D0/SPI0_SEL4B/MIS0_CD/SMC0_ADDR4_Z: length 45.3
  TOP w0.14: v1(28.57,35.37) 28.51,35.44 28.51,36 28.76,36.25 28.77,36.25 28.84,36.33 U20.5 ; U12.5 22.35,36.33 v1(22.1,36.07)
  TOP w0.203: v1(41.02,46.94) U1.V20
  L7_SIG w0.127: v1(28.57,35.37) 27.92,35.37 27.8,35.48 22.68,35.48 v1(22.1,36.07) 21.53,36.64 21.53,38.93 22.34,39.74 24.08,39.74 24.57,39.24 24.96,39.24 27.11,41.4 32,41.4 33.32,42.72 33.32,50.21 33.64,50.53 37.98,50.53 38.21,50.3 38.21,48.4 38.48,48.13 40.37,48.13 41.02,47.49 v1(41.02,46.94)
PC_00/LP1_D1/TWI4_SCL/TRACE0_D04/SPI1_SEL4B: length 47.2
  TOP w0.203: v1(41.02,46.14) U1.W20
  L7_SIG w0.127: v1(41.02,46.14) 41.81,46.14 42.1,45.85 42.1,45.02 41.47,44.39 41.47,29.08 44.96,25.59 44.96,16.76 42.93,14.73 42.93,9.91 45.21,7.62 v1(45.21,5.33)
  BOTTOM w0.14: J2.94 45.21,6.61 v1(45.21,5.33)
PC_01/LP1_D2/TWI4_SDA/TRACE0_D05/SPI2_SEL4B: length 49.8
  TOP w0.203: v1(40.22,46.94) U1.V19
  L7_SIG w0.127: v1(44.2,5.33) 44.7,4.83 45.59,4.83 46.36,5.59 46.36,10.48 45.53,11.3 45.53,26.35 42.11,29.77 42.11,32.02 42.53,32.44 42.53,46.05 42.06,46.53 40.86,46.53 40.86,46.53 40.63,46.53 v1(40.22,46.94)
  BOTTOM w0.14: v1(44.2,5.33) 44.5,5.64 J2.92
PC_02/LP1_D3/TWI5_SCL/TRACE0_D06/SPI1_SEL6B: length 46.4
  TOP w0.203: v1(38.62,46.94) U1.V17
  L7_SIG w0.127: v1(38.62,46.94) 39.02,46.54 39.02,44.83 40.81,43.05 40.81,27.03 38.73,24.96 38.73,22.1 38.82,22.01 38.82,17.65 42.1,14.37 42.1,7.62 42.29,7.43 42.86,7.43 v1(43.56,8.13)
  BOTTOM w0.14: J2.90 43.86,7.83 v1(43.56,8.13)
PC_03/LP1_D4/TWI5_SDA/TRACE0_D07/SPI2_SEL6B: length 49.4
  TOP w0.203: v1(37.82,47.74) U1.U16
  L7_SIG w0.127: v1(37.82,47.74) 37.42,47.34 37.42,44.91 40.14,42.18 40.14,30.07 38.34,28.27 38.34,26.17 37.08,24.92 37.08,18.45 38.53,17 38.53,10.98 40.83,8.68 40.83,7.68 v1(43.18,5.33)
  BOTTOM w0.14: v1(43.18,5.33) 43.18,6.64 J2.88
PC_04/LP1_D5/OSPI_SEL2B/SMC0_ADDR5: length 44.7
  TOP w0.203: v1(39.42,47.74) U1.U18
  L7_SIG w0.127: v1(42.55,8.13) 42.55,14.86 44.63,16.94 44.63,23.13 41.14,26.62 41.14,43.51 39.82,44.83 39.82,47.34 v1(39.42,47.74)
  BOTTOM w0.14: J2.86 42.55,6.73 v1(42.55,8.13)
PC_05/LP1_D6/OSPI_SEL3B/TM0_TMR8/SMC0_ADDR6: length 55.9
  TOP w0.203: v1(37.82,50.14) U1.P16
  L7_SIG w0.127: v1(42.42,5.33) 41.97,4.89 39.69,4.89 38.3,6.27 38.3,7.44 38.29,7.45 38.29,9.82 37.83,10.27 37.83,16.77 36.13,18.47 36.13,28.57 38.04,30.48 38.04,32.59 37.27,33.36 37.27,35.76 36.39,36.65 36.39,37.01 37.22,37.84 37.22,41.03 36.45,41.8 36.45,43.56 36.61,43.72 36.61,44.3 35.82,45.09 35.82,49.54 36.02,49.74 37.46,49.74 v1(37.82,50.14)
  BOTTOM w0.14: J2.84 41.96,5.79 v1(42.42,5.33)
PC_06/LP1_D7/SPI1_RDY/MSI0_WP/SMC0_ADDR7: length 51.2
  TOP w0.203: v1(37.82,49.34) U1.R16
  L7_SIG w0.127: v1(41.53,5.33) 38.67,8.19 38.67,9.9 38.16,10.41 38.16,16.91 36.46,18.61 36.46,26.96 39.05,29.55 39.05,30.67 38.93,30.8 38.93,33.68 37.97,34.63 37.97,39.56 38.23,39.81 38.23,41.53 36.94,42.82 36.94,44.44 36.62,44.75 36.62,48.74 36.82,48.94 37.42,48.94 v1(37.82,49.34)
  BOTTOM w0.14: v1(41.53,5.33) 41.32,5.54 J2.82
PC_07/LP1_CLK/OSPI_SEL4B/TM0_TMR9/SYS_FAULT: length 48.5
  TOP w0.203: v1(38.62,48.54) U1.T17
  L7_SIG w0.127: v1(38.62,48.54) 39.03,48.95 40.36,48.95 40.61,48.7 40.61,48.4 40.86,48.15 40.94,48.15 41.65,47.44 43.24,47.44 43.56,47.12 43.56,37.66 44.26,36.96 44.26,33.34 45.85,31.75 45.85,26.5 45.86,26.49 45.86,11.61 47.12,10.35 v1(47.12,8.13)
  BOTTOM w0.14: v1(47.12,8.13) 47.12,6.76 J2.100
PC_08/OSPI0_CLK/PPI0_D16: length 55
  TOP w0.203: U1.M4 v1(27.42,51.74)
  L5_SIG w0.127: v1(1.4,18.03) 2.54,19.18 2.54,24.51 3.05,25.02 5.97,25.02 6.48,25.53 6.48,31.24 8.83,33.59 8.83,35.15 9.46,35.78 9.46,38.85 9.75,39.14 9.75,40.48 9.53,40.7 9.53,42.61 10.1,43.18 10.1,43.22 10.11,43.23 10.11,44.53 10.52,44.93 11.02,44.93 11.33,45.24 11.33,45.75 13.18,47.6 15.72,47.6 19.05,50.93 19.78,50.93 20.78,50.93 24.48,50.93 24.89,51.34 27.02,51.34 v1(27.42,51.74)
  BOTTOM w0.14: v1(1.4,18.03) 3.05,18.03 J3.83
PC_09/OSPI0_D3/PPI0_D17: length 39.1
  TOP w0.203: v1(25.82,49.34) U1.R2
  L5_SIG w0.127: v1(8.26,24.64) 9.14,25.53 9.14,30.92 9.86,31.64 9.86,34.71 11.54,36.4 11.54,41.87 12.2,42.53 12.2,44.14 14.65,46.59 18.4,46.59 19.11,47.31 21.27,47.31 22.61,48.64 24,48.64 24.7,49.34 v1(25.82,49.34)
  BOTTOM w0.14: J3.62 8,24.89 v1(8.26,24.64)
PC_10/OSPI0_D2/PPI0_D18: length 45.4
  TOP w0.203: U1.U1 v1(25.02,47.74)
  L5_SIG w0.127: v1(25.02,47.74) 24.52,47.24 22.29,47.24 20.84,45.8 16.21,45.8 13.77,43.36 13.77,41.55 12.2,39.99 12.2,35.06 10.57,33.43 10.57,31.2 10.03,30.67 10.03,21.97 9.4,21.34 7.49,21.34 5.84,22.99 5.21,22.99 4.95,23.24 4.95,23.88 v1(5.46,24.38)
  BOTTOM w0.14: v1(5.46,24.38) 5.59,24.26 J3.64
PC_11/OSPI0_MOSI/PPI0_D19: length 44.6
  TOP w0.203: U1.N4 v1(27.42,50.94)
  L5_SIG w0.127: v1(5.46,23.49) 6.48,23.49 6.98,24 6.98,31.28 9.16,33.45 9.16,35.01 9.79,35.65 9.79,38.72 10.08,39 10.08,39.94 10.65,40.52 10.65,43.42 11.49,44.26 11.49,44.45 14.31,47.27 15.94,47.27 18.74,50.07 23.91,50.07 24.38,50.54 27.02,50.54 v1(27.42,50.94)
  BOTTOM w0.14: v1(5.46,23.49) 5.59,23.62 J3.66
PC_12/OSPI0_MISO/PPI0_D20: length 44.5
  TOP w0.203: U1.P3 v1(26.62,50.14)
  L5_SIG w0.127: v1(26.62,50.14) 26.22,49.74 20.63,49.74 17.83,46.94 14.53,46.94 11.87,44.28 11.87,44.26 11.84,44.23 11.84,42.64 11.11,41.91 11.11,40.51 10.41,39.81 10.41,38.87 10.12,38.58 10.12,35.51 9.49,34.87 9.49,32.22 8.64,31.37 8,31.37 7.75,31.11 7.75,23.69 8.06,23.37 v1(9.14,23.37)
  BOTTOM w0.14: v1(9.14,23.37) 8.76,22.99 J3.68
PC_13/OSPI0_D7/PPI0_D21: length 41.3
  TOP w0.203: U1.T2 v1(25.82,48.54)
  L5_SIG w0.127: v1(25.82,48.54) 25.41,48.13 25.18,48.13 24.13,48.13 23.95,48.31 22.78,48.31 21.4,46.93 19.24,46.93 18.57,46.26 14.83,46.26 12.53,43.97 12.53,42.39 12.8,42.13 12.8,41.05 11.87,40.12 11.87,35.2 10.21,33.54 10.21,31.42 9.65,30.86 9.65,23.11 v1(9.14,22.61)
  BOTTOM w0.14: v1(9.14,22.61) 8.89,22.35 J3.70
PC_14/OSPI0_D6/PPI0_D22: length 98
  TOP w0.203: v1(25.02,46.94) U1.V1
  L5_SIG w0.127: v1(5.46,22.48) 5.46,21.46 6.1,20.83 9.5,20.83 13.21,24.53 13.21,26.42 12.83,26.8 12.83,29.46 11.06,31.23 11.06,32.27 11.42,32.63 12.69,32.63 13.02,32.96 13.02,33.97 12.53,34.46 12.53,39.78 14.1,41.34 14.1,43.18 16.38,45.47 23.11,45.47 24.59,46.94 24.59,46.94 v1(25.02,46.94)
  L8_SIG w0.127: v1(61.72,39.75) 62.23,40.26 62.23,47.14 61.53,47.84 54.62,47.84 53.35,46.57 48.86,46.57 48.72,46.43 42.92,46.43 42.81,46.54 33.59,46.54 33.01,47.12 33.01,48.3 32.38,48.93 25.66,48.93 25.41,48.67 25.41,47.33 v1(25.02,46.94)
  BOTTOM w0.14: J3.72 5.71,21.72 5.46,21.97 v1(5.46,22.48) ; J1.85 61.47,39.5 v1(61.72,39.75)
PC_15/OSPI0_D5/PPI0_D23: length 88.8
  TOP w0.203: v1(28.22,50.94) U1.N5
  L5_SIG w0.127: v1(28.57,34.42) 28.06,34.93 28.06,35.18 28.05,35.19 28.05,35.23 27.8,35.48 27.38,35.48 26.9,35.97 26.9,37.57 27.44,38.11 27.44,38.74 27.93,39.23 27.93,40.49 27.93,44.13 27.02,45.04 27.02,48.01 27.15,48.13 27.69,48.13 27.81,48.26 27.81,50.53 v1(28.22,50.94) ; v1(53.85,40.26) 52.81,41.29 52.81,45.85 v1(51.62,47.04)
  L7_SIG w0.127: v1(8.38,21.84) 8.89,21.34 11.18,21.34 12.83,22.99 20.64,22.99 26.09,28.44 26.09,29.73 25.15,30.68 25.15,32.83 26.29,33.98 28.13,33.98 v1(28.57,34.42)
  L8_SIG w0.127: v1(51.62,47.04) 51.25,47.41 42.88,47.41 42.81,47.34 33.46,47.34 33.34,47.47 33.34,49.67 32.47,50.54 28.62,50.54 v1(28.22,50.94)
  BOTTOM w0.14: v1(8.38,21.84) 8.38,21.34 8.13,21.08 J3.74 ; v1(53.85,40.26) 54.24,40.26 54.68,39.81 55.12,39.81 55.43,39.5 J1.86
PD_00/OSPI0_D4: length 50.9
  TOP w0.203: U1.U2 v1(25.82,47.74)
  L4_SIG w0.127: v1(25.82,47.74) 25.42,47.34 24.82,47.34 24.62,47.14 24.62,44.58 24.83,44.37 24.83,40.85 25.13,40.55 25.13,38.89 23.49,37.25 23.49,28.38 25.97,25.91 25.97,18.16 25.65,17.84 25.65,15.49 26.16,14.99 26.16,9.91 26.8,9.27 26.8,7.43 28.45,5.78 30.8,5.78 v1(31.24,5.33)
  BOTTOM w0.14: J2.50 31.24,6.61 v1(31.24,5.33)
